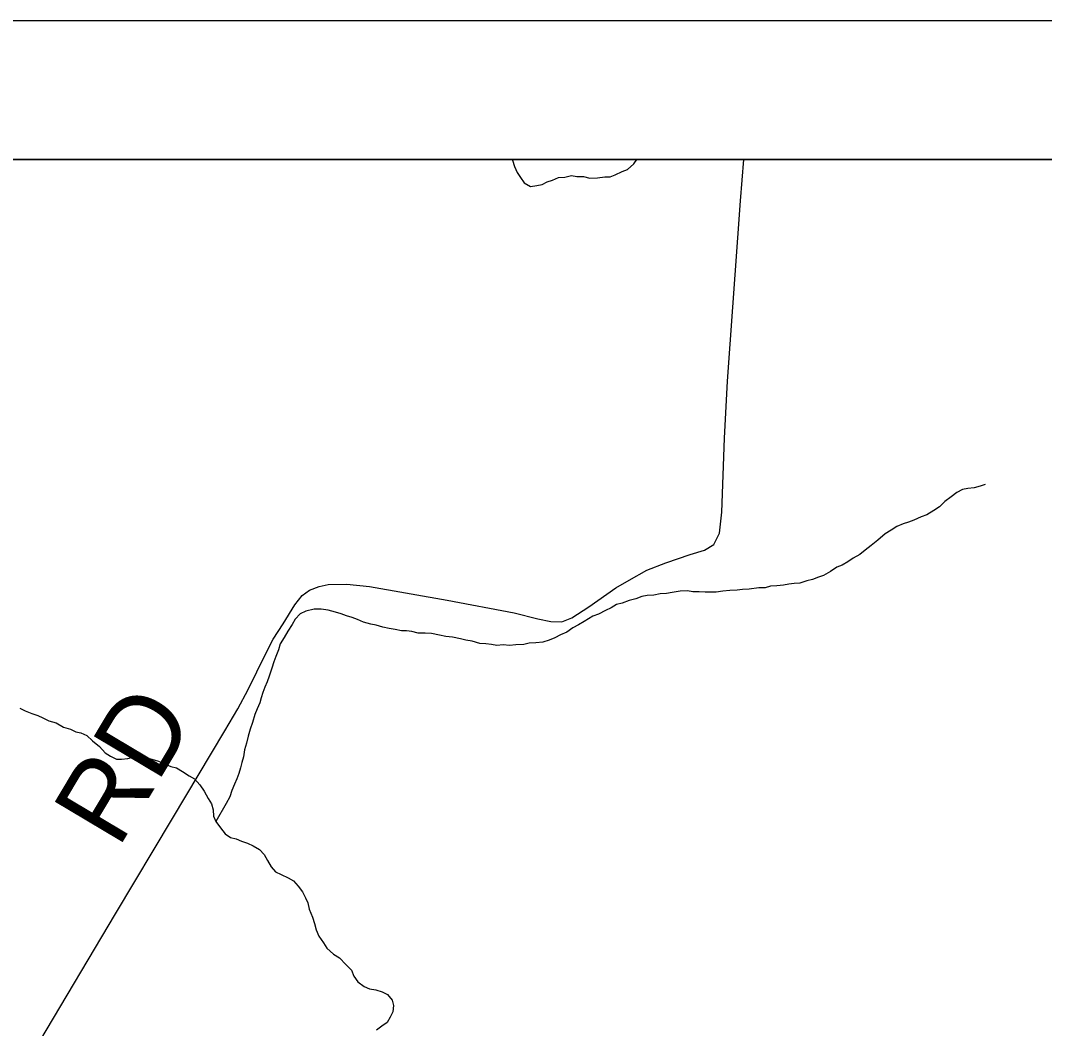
# Model space of a CAD drawing. Extents: x -13.7 to 34, y 0 to 32.3.
# Drawn here: x 29.098 to 29.835, y 20.274 to 21 of the extents above; entities that cross this region are included whole.
import ezdxf

# ---------------------------------------------------------------- set-up
doc = ezdxf.new("R2010")
doc.units = 0
for name, color, linetype in [('GM_X_Corporation', 7, 'Continuous'), ('GM_X_Minor_River', 7, 'Continuous'), ('GM_X_Township_Road', 7, 'Continuous'), ('GM_X_Township_Road_Text', 7, 'Continuous'), ('SH_Data', 7, 'Continuous')]:
    doc.layers.add(name, color=color, linetype=linetype)

msp = doc.modelspace()

# ---------------------------------------------------------------- linework, layer by layer
at = {"layer": 'GM_X_Corporation'}
for points in [[(25.54914, 14.1), (30.31667, 14.1), (30.31667, 20.877), (30.27752, 20.87955), (29.95979, 20.9), (26.00265, 20.9)], [(27.68856, 14.89624), (28.65533, 14.83542), (29.70192, 14.77554), (30.31667, 14.73543), (30.31667, 20.877), (30.27752, 20.87955), (29.95979, 20.9), (26.00265, 20.9)]]:
    msp.add_lwpolyline(points, dxfattribs=at)
at = {"layer": 'GM_X_Minor_River'}
for points in [[(29.45158, 20.9), (29.45186, 20.89931), (29.4534, 20.89476), (29.45531, 20.89059), (29.4576, 20.8868), (29.46026, 20.88301), (29.46483, 20.88037), (29.46938, 20.88114), (29.47318, 20.88191), (29.47697, 20.88382), (29.48076, 20.88496), (29.48494, 20.88687), (29.48949, 20.88726), (29.49443, 20.88841), (29.49822, 20.88766), (29.50316, 20.88767), (29.50772, 20.88655), (29.51304, 20.88656), (29.51835, 20.88733), (29.52215, 20.88734), (29.52594, 20.88887), (29.53087, 20.89116), (29.53466, 20.89268), (29.53921, 20.89687), (29.54148, 20.9)], [(29.79235, 20.66572), (29.78856, 20.66457), (29.78438, 20.66343), (29.77983, 20.66304), (29.77603, 20.66227), (29.77186, 20.65998), (29.76769, 20.65694), (29.76315, 20.65351), (29.75936, 20.64971), (29.75519, 20.64704), (29.75026, 20.644), (29.74609, 20.64247), (29.74078, 20.64018), (29.73698, 20.63865), (29.73319, 20.6375), (29.72864, 20.63559), (29.72447, 20.63293), (29.7203, 20.63026), (29.71499, 20.6257), (29.71007, 20.62189), (29.7059, 20.61847), (29.70211, 20.61542), (29.69718, 20.61276), (29.69339, 20.61009), (29.68922, 20.6078), (29.68543, 20.60628), (29.68088, 20.60323), (29.67595, 20.60018), (29.67215, 20.59904), (29.66798, 20.59751), (29.66381, 20.59636), (29.65887, 20.59483), (29.6547, 20.59444), (29.6509, 20.59405), (29.64711, 20.59328), (29.64217, 20.59289), (29.63762, 20.5925), (29.63382, 20.59135), (29.62927, 20.59134), (29.62243, 20.59057), (29.6175, 20.59017), (29.6137, 20.58979), (29.60839, 20.58939), (29.60345, 20.589), (29.59852, 20.58823), (29.59434, 20.58822), (29.59054, 20.58821), (29.58636, 20.58858), (29.58181, 20.58857), (29.57801, 20.58932), (29.57269, 20.58892), (29.567, 20.58815), (29.56282, 20.58738), (29.55827, 20.58699), (29.55371, 20.58622), (29.54878, 20.58583), (29.54498, 20.58506), (29.54081, 20.58353), (29.53587, 20.58238), (29.53094, 20.58047), (29.52677, 20.57932), (29.52298, 20.57704), (29.51881, 20.57513), (29.51388, 20.57247), (29.5097, 20.57094), (29.50364, 20.56713), (29.49947, 20.56484), (29.4953, 20.56255), (29.49113, 20.55951), (29.48658, 20.5576), (29.4824, 20.55532), (29.47823, 20.55379), (29.47368, 20.55226), (29.46874, 20.55187), (29.46381, 20.55147), (29.46001, 20.55071), (29.45432, 20.55031), (29.44976, 20.54992), (29.4452, 20.55029), (29.44065, 20.5499), (29.43685, 20.55065), (29.43267, 20.55102), (29.42849, 20.55139), (29.42279, 20.55289), (29.41823, 20.55364), (29.41443, 20.55476), (29.40874, 20.55589), (29.4038, 20.55626), (29.39924, 20.55738), (29.39354, 20.5585), (29.38898, 20.55887), (29.38404, 20.55886), (29.37948, 20.55999), (29.37568, 20.56036), (29.37189, 20.56035), (29.36733, 20.56147), (29.36315, 20.56222), (29.35859, 20.56297), (29.35365, 20.56447), (29.34985, 20.56522), (29.34453, 20.56673)], [(29.34453, 20.56673), (29.34035, 20.56861), (29.33655, 20.57012), (29.33237, 20.57125), (29.32857, 20.57276), (29.32439, 20.57388), (29.31907, 20.57539), (29.31413, 20.57613), (29.30919, 20.57612), (29.30312, 20.57459), (29.29895, 20.57268), (29.29554, 20.56888), (29.29327, 20.56508), (29.29025, 20.56014), (29.2876, 20.55558), (29.28458, 20.55102), (29.28345, 20.54685), (29.28156, 20.54191), (29.28005, 20.53812), (29.27855, 20.53356), (29.27666, 20.52787), (29.27515, 20.52369), (29.27365, 20.51989), (29.27214, 20.5161), (29.27101, 20.5123), (29.26988, 20.5085), (29.26799, 20.50433), (29.26648, 20.50015), (29.2646, 20.49446), (29.26309, 20.48952), (29.26159, 20.48459), (29.26046, 20.47965), (29.25896, 20.47472), (29.25821, 20.46978), (29.25708, 20.46561), (29.25595, 20.46181), (29.25482, 20.45764), (29.25331, 20.45384), (29.25181, 20.45004), (29.24992, 20.44549), (29.24841, 20.44093), (29.24577, 20.43599), (29.23825, 20.42302)], [(29.09711, 20.50466), (29.10091, 20.50277), (29.10585, 20.50088), (29.11004, 20.49938), (29.11384, 20.49787), (29.11802, 20.49561), (29.12334, 20.4941), (29.12866, 20.49108), (29.13361, 20.48957), (29.13741, 20.48769), (29.14121, 20.48694), (29.14539, 20.48505), (29.14958, 20.48127), (29.15452, 20.47711), (29.15871, 20.47257), (29.16252, 20.4703), (29.1667, 20.46804), (29.1705, 20.46805), (29.17505, 20.46844), (29.17923, 20.46959), (29.18302, 20.4696), (29.18758, 20.46923), (29.19214, 20.4681), (29.19708, 20.4666), (29.20126, 20.46471), (29.20583, 20.46282), (29.21001, 20.4617), (29.21419, 20.45905), (29.21913, 20.45603), (29.22294, 20.45376), (29.22674, 20.4496), (29.22979, 20.44506), (29.23285, 20.43975), (29.23514, 20.43597), (29.23629, 20.43142), (29.23668, 20.42687), (29.23821, 20.42308), (29.24164, 20.41854), (29.24507, 20.41437), (29.24887, 20.41173), (29.25305, 20.4106), (29.25685, 20.40909), (29.26103, 20.40758), (29.26522, 20.4057), (29.26978, 20.40305), (29.27321, 20.39927), (29.2755, 20.3951), (29.27817, 20.39056), (29.28121, 20.38677), (29.2854, 20.38489), (29.29034, 20.38262), (29.29414, 20.38036), (29.29757, 20.37657), (29.30062, 20.37241), (29.30291, 20.36824), (29.30444, 20.36445), (29.30559, 20.3599), (29.30788, 20.35422), (29.30941, 20.34967), (29.31056, 20.34512), (29.31247, 20.34058), (29.3159, 20.33566), (29.31819, 20.33187), (29.32314, 20.32771), (29.32732, 20.32506), (29.33189, 20.32015), (29.33608, 20.31598), (29.33761, 20.31182), (29.34066, 20.30765), (29.34523, 20.30425), (29.34903, 20.30274), (29.35359, 20.30199), (29.35815, 20.30049), (29.36195, 20.2986), (29.36538, 20.29444), (29.36615, 20.29065), (29.36578, 20.28609), (29.36389, 20.28229), (29.36162, 20.2785), (29.35783, 20.27583), (29.35404, 20.27279)]]:
    msp.add_lwpolyline(points, dxfattribs=at)
at = {"layer": 'GM_X_Township_Road'}
msp.add_lwpolyline([(29.11153, 20.26494), (29.16615, 20.35656), (29.20707, 20.42528), (29.24485, 20.48852), (29.25425, 20.50438), (29.26169, 20.51808), (29.27402, 20.54373), (29.2797, 20.5545), (29.28675, 20.56546), (29.29517, 20.57916), (29.30045, 20.58582), (29.30574, 20.58973), (29.31259, 20.59228), (29.31924, 20.59385), (29.33256, 20.59404), (29.349, 20.59228), (29.40499, 20.58249), (29.45316, 20.57329), (29.47019, 20.56899), (29.47958, 20.56722), (29.48742, 20.56702), (29.49466, 20.56977), (29.5068, 20.57779), (29.52638, 20.5915), (29.53597, 20.59698), (29.54869, 20.60402), (29.5624, 20.60951), (29.57982, 20.61538), (29.5902, 20.61851), (29.59685, 20.62262), (29.60097, 20.63085), (29.60273, 20.64592), (29.60449, 20.69918), (29.60665, 20.74028), (29.616, 20.87013), (29.61843, 20.9)], dxfattribs=at)
at = {"layer": 'SH_Data'}
for points in [[(23.41667, 21), (30.41667, 21), (30.41667, 14), (23.41667, 14)], [(23.51667, 20.9), (30.31667, 20.9), (30.31667, 14.1), (23.51667, 14.1)]]:
    msp.add_lwpolyline(points, close=True, dxfattribs=at)

# ---------------------------------------------------------------- texts
at = {"layer": 'GM_X_Township_Road_Text'}
msp.add_text('RD', height=0.056818, rotation=59.20732, dxfattribs=at).set_placement((29.168, 20.40293))

doc.saveas('drawing.dxf')
